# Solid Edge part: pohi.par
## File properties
Author: Cymax
Template: Normal.par
Last saved by: Cymax
Revision: 26
Application: Solid Edge
Accuracy: 0,990
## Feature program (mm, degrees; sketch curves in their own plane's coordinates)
swept protrusion "unnamed SweptProtrusion 1"
fillet "Round_3" radius 150
thinwall "Thinwall_2"  Thickness = 100 mm
sketch for "ExtrudedProtrusion_3" plane through (0, 0, 0) normal (0, 0, 1) x-axis (1, 0, 0)
extrude "ExtrudedProtrusion_3" add finite 1 along -normal
logasc func "Lip_Groove_4"  LipOrGrooveWidth = 100 mm; LipOrGrooveHeight = 40 mm
fillet "Round_6" radius 130  Radii2 = 130 mm
sketch used by "ExtrudedCutout_2" plane through (-25.8677, 0, 0) normal (0, 0, 1) x-axis (1, 0, 0)
extrude "ExtrudedCutout_2" cut finite 1 along -normal
web network "WebNetwork_1"  Profile_Plane1_Distance = 1065.3839 mm
sketch used by "unnamed Cutout 1" plane through (0, 0, 40) normal (0, 0, 1) x-axis (1, 0, 0)
extrude "unnamed Cutout 1" cut to key point along -normal
sketch for "ExtrudedCutout_5" #1 plane through (-468.8657, 0.5873, -1500) normal (0, 0, -1) x-axis (0, 1, 0)
sketch for "ExtrudedCutout_5" #2 plane through (-468.8657, 0.5873, -1500) normal (0, 0, -1) x-axis (0, 1, 0)
  circle centre (-0.5873, -815.6019) radius 75
  dimension (linear) = 0.5873
extrude "ExtrudedCutout_5" cut finite 90 along -normal
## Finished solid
Body 1: solid body, 71 faces, 190 edges, 124 vertices.
  Faces by surface: plane 36, cylinder 17, blend 8, offset 5, spline 5
  Edges by curve: intersection 80, line 71, circle 38, spline 1
Bounding box of the edges (mm; curved faces can reach further): 7200.000 x 2017.569 x 1540.000, from (-3600, -1007.3937, -1500) to (3600, 1010.1757, 40).
Cylindrical faces by radius (mm): R75 x3, R130 x2, R225 x4, R3780 x2, R3880 x2, R6910 x2, R7010 x2
Planar faces by outward normal: +x 3, +y 4, +z 8, -x 3, -y 4, -z 4, oblique 10
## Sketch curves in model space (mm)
circle centre (423.445, 0, 40) radius 75
line (-3500, -431.9019, 0) -> (-3500, 431.9019, 0)
arc centre (-1000, 6010, 0) radius 6910 from (-3500, -431.9019, 0) through (-2271.7228, -781.9674, 0) to (-1000, -900, 0)
line (1000, -900, 0) -> (-1000, -900, 0)
arc centre (1000, 2880, 0) radius 3780 from (3448.2647, 0, 0) through (2304.2239, -667.8726, 0) to (1000, -900, 0)
arc centre (1000, -2880, 0) radius 3780 from (1000, 900, 0) through (2304.2239, 667.8726, 0) to (3448.2647, 0, 0)
line (-1000, 900, 0) -> (1000, 900, 0)
arc centre (-1000, -6010, 0) radius 6910 from (-1000, 900, 0) through (-2271.7228, 781.9674, 0) to (-3500, 431.9019, 0)
arc centre (-1584.4676, 9250.471, -1500) radius 9518.1716 from (-1584.4676, -267.7006, -1500) through (-455.747, -200.5385, -1500) to (657.0446, 0, -1500)
arc centre (-1584.4676, -9250.471, -1500) radius 9518.1716 from (-1584.4676, 267.7006, -1500) through (-455.747, 200.5385, -1500) to (657.0446, 0, -1500)
line (-1584.4676, 267.7006, -1500) -> (-1584.4676, -267.7006, -1500)
line (0, 1000, 0) -> (0, -1000, 0)
line (-3600, 0, 0) -> (3600, 0, 0)
arc centre (-1000, 6010, 0) radius 7010 from (-1000, -1000, 0) through (-2323.8202, -873.8652, 0) to (-3600, -500, 0)
line (1000, -1000, 0) -> (-1000, -1000, 0)
arc centre (1000, 2880, 0) radius 3880 from (1000, -1000, 0) through (2392.8388, -741.381, 0) to (3600, 0, 0)
arc centre (1000, -2880, 0) radius 3880 from (1000, 1000, 0) through (2392.8388, 741.381, 0) to (3600, 0, 0)
line (1000, 1000, 0) -> (-1000, 1000, 0)
arc centre (-1000, -6010, 0) radius 7010 from (-1000, 1000, 0) through (-2323.8202, 873.8652, 0) to (-3600, 500, 0)
line (-3600, 500, 0) -> (-3600, -500, 0)
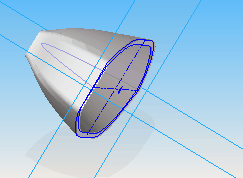
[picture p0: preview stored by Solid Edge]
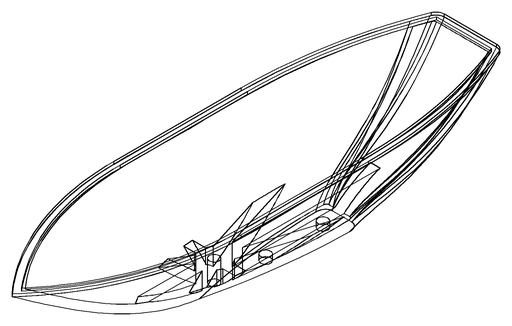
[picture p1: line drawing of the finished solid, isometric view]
